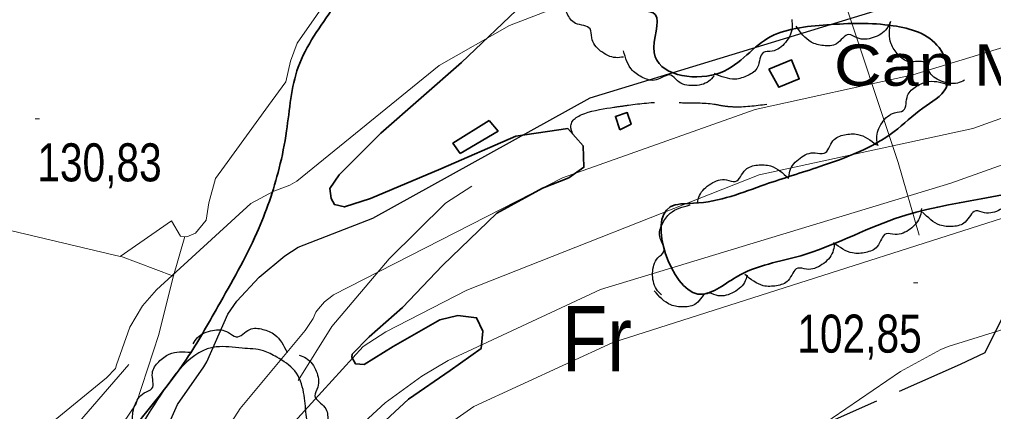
# Model space of a CAD drawing. Extents: x 483843 to 488449, y 4381269 to 4384483.
# Drawn here: x 486483.2 to 486707.3, y 4383232.7 to 4383322.9 of the extents above; entities that cross this region are included whole.
import ezdxf
from ezdxf.enums import TextEntityAlignment as Align

# ---------------------------------------------------------------- set-up
doc = ezdxf.new("R2010")
doc.units = 0
doc.header["$LTSCALE"] = 3.8
doc.linetypes.add('LONG_DASHED', pattern=[7.5, 6, -1.5])
for name, color, linetype, lineweight in [('13', 7, 'Continuous', 35), ('25', 7, 'LONG_DASHED', 25), ('27', 7, 'Continuous', 25), ('38', 7, 'Continuous', 25), ('47', 7, 'Continuous', 35), ('51', 7, 'Continuous', 13), ('6', 7, 'Continuous', 35), ('7', 7, 'Continuous', 13), ('8', 7, 'Continuous', 25), ('9', 7, 'Continuous', 13)]:
    doc.layers.add(name, color=color, linetype=linetype, lineweight=lineweight)
doc.layers.add('31', color=7, linetype='Continuous')
doc.layers.add('5', color=7, linetype='Continuous')

msp = doc.modelspace()

# ---------------------------------------------------------------- linework, layer by layer
at = {"layer": '13'}
msp.add_spline([(486780.88, 4383404.79), (486794.13, 4383455.03), (486806.75, 4383492.74), (486812.33, 4383499.64), (486814.71, 4383503.51), (486819.41, 4383506.81), (486825.21, 4383508.61), (486829.49, 4383508.62), (486831.66, 4383508.22), (486834.79, 4383506.67), (486839.23, 4383502.48), (486841.25, 4383491.57), (486838.33, 4383465.65), (486835.59, 4383431.7), (486834, 4383420.31), (486833.25, 4383414.77), (486832.97, 4383406.37), (486832.3, 4383401.5), (486829.47, 4383397.12), (486823.83, 4383396.67), (486809.94, 4383396.27), (486802.97, 4383396.6), (486796, 4383397.37), (486791.44, 4383398.19), (486788.79, 4383396.8), (486785.88, 4383392.64), (486784.6, 4383386.95), (486784.53, 4383376.98), (486784.84, 4383372.17), (486782.2, 4383361.03), (486774.71, 4383351.45), (486769.08, 4383335.85), (486761.59, 4383315.77), (486757.7, 4383301.05), (486738.21, 4383291.87), (486723.87, 4383286.22), (486684.72, 4383277.1), (486662.99, 4383268.56), (486648.14, 4383263.67), (486639.3, 4383259.75), (486632.91, 4383279.8), (486638.33, 4383280.62), (486654.82, 4383284.96), (486667.34, 4383289.06), (486684.49, 4383297.14), (486691.09, 4383302.53), (486696.41, 4383307.18), (486694.82, 4383316.43), (486684.24, 4383321.46), (486669.01, 4383321.68), (486655.38, 4383318.57), (486643.48, 4383310.34), (486629.22, 4383315.27), (486629.5, 4383324.04), (486622.3, 4383324.82), (486616.85, 4383326.7), (486612.21, 4383337.87), (486614.37, 4383347.45), (486644.42, 4383349.27), (486649.2, 4383384.92), (486651.66, 4383388.63), (486652.89, 4383395.9), (486652.14, 4383401.38), (486671.78, 4383415.81), (486678.55, 4383411.44), (486675.33, 4383401.28), (486669.84, 4383395.35), (486659.1, 4383373.67), (486670.12, 4383362.71), (486675.25, 4383359.48), (486683.36, 4383359.82), (486702.12, 4383364.88), (486729.49, 4383379.19), (486744.12, 4383389.71), (486750.48, 4383393.52), (486749.77, 4383396.53), (486731.96, 4383399.94), (486712.51, 4383419.8), (486725.33, 4383419.24), (486752.3, 4383411.05), (486765.39, 4383408.24), (486770.85, 4383407.04), (486780.7, 4383403.07)], degree=3, dxfattribs=at)
at = {"layer": '25'}
msp.add_lwpolyline([(486625.97, 4383203.81), (486659.6, 4383225.99), (486699.78, 4383243.65), (486705.44, 4383246.34), (486713.56, 4383262.73), (486722.5, 4383263.73), (486732.81, 4383265.76), (486750.38, 4383266.41), (486752.13, 4383263.16)], dxfattribs=at)
at = {"layer": '27'}
for points in [[(486610.86, 4384044.96), (486626.92, 4384050.28), (486637.16, 4384047.74), (486652.05, 4384044.37), (486668.53, 4384042.49), (486656.8, 4383988.7), (486633.28, 4383928.86), (486626.29, 4383912.38), (486620.95, 4383890.47), (486618.98, 4383873.39), (486617.47, 4383861.93), (486622.54, 4383859.83), (486631.45, 4383858.8), (486644.63, 4383856.29), (486649.12, 4383845.49), (486645.98, 4383835.48), (486644.53, 4383823.42), (486643.59, 4383804.83), (486644.04, 4383789.06), (486650.17, 4383776.97), (486661.43, 4383767.05), (486666.65, 4383759.32), (486665.61, 4383749.81), (486664.24, 4383748.18), (486659.87, 4383747.12), (486650.35, 4383747.78), (486629.58, 4383749.13), (486612.5, 4383751.02), (486592.66, 4383759.56), (486583.46, 4383745.88), (486580.74, 4383723.11), (486572.16, 4383689.84), (486560.68, 4383659.02), (486553.32, 4383631.81), (486543.18, 4383605.32), (486532.56, 4383576.21), (486523.53, 4383553.45), (486518.77, 4383540.54), (486501.4, 4383543.49), (486476.15, 4383556.3), (486468.29, 4383557.62), (486465.07, 4383557.96), (486462.29, 4383558.08), (486460.26, 4383557.81), (486439.29, 4383544.45), (486415.17, 4383526.49), (486391.53, 4383510.54), (486385.69, 4383506.57), (486377.62, 4383503.39), (486371.16, 4383503.41), (486344.21, 4383501.99), (486329.53, 4383482.99), (486328.89, 4383480.37), (486326.87, 4383475.75), (486312.85, 4383471.45), (486300.33, 4383482.51), (486290.76, 4383490.08), (486283.31, 4383493.56), (486272.61, 4383495.89), (486284, 4383520.94), (486252.05, 4383537.68), (486229.62, 4383543.55), (486216.83, 4383551.46), (486203.95, 4383558.48), (486174.8, 4383524.83), (486205.26, 4383519.21), (486220.9, 4383511.34), (486230.24, 4383508.13), (486241.13, 4383503.92), (486264.65, 4383495.7), (486250.48, 4383465.06), (486236.28, 4383432.55), (486231.27, 4383423.25), (486225.77, 4383410.64), (486214.94, 4383382.73), (486214.23, 4383380.42), (486219.38, 4383373.59), (486258.75, 4383355.69), (486297.13, 4383332.33), (486352.51, 4383306.4), (486336.13, 4383294.48), (486320.46, 4383268.89), (486317.3, 4383262.94), (486310.85, 4383257.93), (486295.11, 4383254.25), (486285.76, 4383251.31), (486282.23, 4383245.35), (486279.78, 4383236.83), (486280.35, 4383218.97), (486309.23, 4383192.29), (486315, 4383181.33)], [(486622.16, 4383314.27), (486620.38, 4383314.12), (486616.92, 4383315.65), (486614.86, 4383318.71), (486614.49, 4383320.74), (486611.17, 4383322.01), (486609.2, 4383324.25), (486608.34, 4383327.14), (486609.58, 4383331.95)], [(486660.89, 4383322.87), (486661.03, 4383321.1), (486659.47, 4383317.64), (486656.38, 4383315.62), (486654.35, 4383315.27), (486653.05, 4383311.96), (486650.79, 4383310.01), (486647.89, 4383309.18), (486643.09, 4383310.45)], [(486683.64, 4383322.4), (486682.81, 4383320.82), (486679.65, 4383318.73), (486675.96, 4383318.66), (486674.06, 4383319.43), (486671.2, 4383317.32), (486668.25, 4383316.88), (486665.34, 4383317.72), (486661.96, 4383321.35)], [(486700.69, 4383308.93), (486699.04, 4383308.28), (486695.27, 4383308.75), (486692.43, 4383311.1), (486691.5, 4383312.93), (486687.95, 4383313.19), (486685.42, 4383314.78), (486683.77, 4383317.31), (486683.57, 4383322.27)], [(486643.08, 4383309.94), (486641.81, 4383308.7), (486638.15, 4383307.69), (486634.62, 4383308.78), (486633.06, 4383310.11), (486629.68, 4383308.99), (486626.74, 4383309.49), (486624.24, 4383311.19), (486622.16, 4383315.7)], [(486680.76, 4383293.81), (486680.46, 4383295.56), (486681.7, 4383299.15), (486684.59, 4383301.44), (486686.57, 4383301.98), (486687.57, 4383305.39), (486689.64, 4383307.54), (486692.46, 4383308.63), (486697.35, 4383307.8)], [(486660.18, 4383286.3), (486660.47, 4383288.05), (486662.81, 4383291.03), (486666.29, 4383292.26), (486668.34, 4383292.12), (486670.4, 4383295.02), (486673.06, 4383296.37), (486676.08, 4383296.48), (486680.43, 4383294.1)], [(486639.19, 4383280.7), (486639.66, 4383282.42), (486642.29, 4383285.14), (486645.88, 4383286.01), (486647.9, 4383285.66), (486650.24, 4383288.34), (486653.03, 4383289.41), (486656.05, 4383289.21), (486660.13, 4383286.4)], [(486712.16, 4383283.52), (486711.63, 4383281.82), (486708.9, 4383279.19), (486705.28, 4383278.46), (486703.27, 4383278.88), (486700.84, 4383276.29), (486698.02, 4383275.32), (486695.01, 4383275.62), (486691.03, 4383278.59)], [(486630.95, 4383259.55), (486629.77, 4383260.87), (486628.89, 4383264.56), (486630.11, 4383268.06), (486631.49, 4383269.56), (486630.51, 4383272.98), (486631.12, 4383275.9), (486632.91, 4383278.33), (486637.49, 4383280.24)], [(486690.76, 4383279.46), (486690.48, 4383277.71), (486688.15, 4383274.71), (486684.67, 4383273.47), (486682.62, 4383273.61), (486680.58, 4383270.69), (486677.92, 4383269.33), (486674.9, 4383269.2), (486670.54, 4383271.57)], [(486670.7, 4383271.14), (486670.33, 4383269.4), (486667.86, 4383266.53), (486664.32, 4383265.46), (486662.28, 4383265.7), (486660.1, 4383262.89), (486657.38, 4383261.66), (486654.36, 4383261.68), (486650.12, 4383264.26)], [(486650.66, 4383264.09), (486650.03, 4383262.44), (486647.14, 4383259.97), (486643.48, 4383259.47), (486641.5, 4383260.02), (486638.91, 4383257.58), (486636.03, 4383256.78), (486633.05, 4383257.28), (486629.26, 4383260.48)], [(486523.13, 4383248.31), (486524.16, 4383249.75), (486527.59, 4383251.39), (486531.25, 4383250.95), (486533.02, 4383249.91), (486536.15, 4383251.61), (486539.14, 4383251.64), (486541.9, 4383250.4), (486544.74, 4383246.34)], [(486566.59, 4383165.19), (486559.21, 4383168.97), (486553.53, 4383170.18), (486550.54, 4383171.05), (486548.38, 4383172.28), (486543.56, 4383175.88), (486541.96, 4383179.65), (486542.24, 4383188.43), (486544.65, 4383204.83), (486548.1, 4383210.1), (486550.36, 4383221.33), (486550.39, 4383223.28), (486549.16, 4383232.07), (486548.56, 4383237.11), (486546.53, 4383242.09), (486542.38, 4383245.23), (486539.32, 4383246.7), (486534.38, 4383247.29), (486528.45, 4383247.6), (486514.92, 4383235.49), (486503.71, 4383217.19), (486497.82, 4383204.75), (486497.38, 4383200.03), (486496.93, 4383194.93), (486495.53, 4383185.95), (486495.78, 4383177.39), (486497.62, 4383169.41), (486498.94, 4383161.81), (486502.02, 4383151.94), (486512.14, 4383135.73), (486514.76, 4383130.14), (486517.17, 4383124.93), (486511.05, 4383122.02), (486506.05, 4383124.49), (486490.82, 4383134.91), (486487.26, 4383137.82), (486455.32, 4383113.66), (486442.37, 4383104.77), (486437.83, 4383086.67), (486430.34, 4383082.5), (486404.07, 4383086.78), (486395.79, 4383090.28), (486389.3, 4383093.22), (486382.29, 4383096.02), (486378.87, 4383098.55), (486381.09, 4383112.25), (486383.37, 4383119.49), (486385.11, 4383130.58), (486386.58, 4383138.73), (486382.65, 4383142.09), (486371.02, 4383149.11)], [(486510.1, 4383228.64), (486509.37, 4383230.26), (486509.66, 4383234.04), (486511.87, 4383237), (486513.65, 4383238.02), (486513.74, 4383241.57), (486515.21, 4383244.17), (486517.65, 4383245.95), (486522.59, 4383246.39)], [(486547.54, 4383245.71), (486549.16, 4383245), (486551.47, 4383241.99), (486551.8, 4383238.31), (486551.16, 4383236.36), (486553.46, 4383233.66), (486554.11, 4383230.74), (486553.47, 4383227.79), (486550.09, 4383224.16)]]:
    msp.add_spline(points, degree=3, dxfattribs=at)
at = {"layer": '38', "linetype": 'LONG_DASHED'}
msp.add_spline([(486610.54, 4383296.52), (486610.09, 4383297.89), (486619.96, 4383302.72), (486623.34, 4383303.2), (486631.76, 4383303.9), (486635.73, 4383303.77), (486643.01, 4383303.44), (486645.33, 4383303.03), (486647.35, 4383302.85), (486655.16, 4383303.42)], degree=3, dxfattribs=at)
at = {"layer": '47'}
for points in [[(486655.65, 4383311.51), (486660.86, 4383313.62), (486662.64, 4383309.22), (486657.94, 4383307.32)], [(486621.31, 4383297.52), (486620.31, 4383300.61), (486623.04, 4383301.5), (486623.91, 4383298.8)]]:
    msp.add_lwpolyline(points, close=True, dxfattribs=at)
for points in [[(486584.62, 4383292.05), (486582.93, 4383294.47), (486591.25, 4383299.68)], [(486591.25, 4383299.68), (486593.32, 4383297.25), (486584.62, 4383292.05)]]:
    msp.add_lwpolyline(points, dxfattribs=at)
at = {"layer": '51'}
for p, q in [((486540.51, 4383303.14), (486530.33, 4383289.17)), ((486540.51, 4383303.14), (486530.33, 4383289.17)), ((486518.61, 4383263.9), (486506.44, 4383268.49)), ((486515.21, 4383250.42), (486510.03, 4383234.51))]:
    msp.add_line(p, q, dxfattribs=at)
for points in [[(486469.1, 4383389.53), (486577.07, 4383362.46), (486555.98, 4383330.28), (486547.09, 4383317.42), (486545.53, 4383313.32), (486544.48, 4383308.6), (486540.51, 4383303.14)], [(486690.22, 4383273.27), (486685.43, 4383290), (486672.13, 4383329.96), (486653.36, 4383381.93), (486649.13, 4383380.26)], [(486437.22, 4383285.73), (486471.24, 4383276.64), (486506.32, 4383268.41), (486518.14, 4383276.57), (486520.19, 4383273.09), (486521.69, 4383272.91), (486523.65, 4383273.79), (486526.09, 4383276.75), (486526.75, 4383280.72), (486528.26, 4383286.33), (486530.33, 4383289.17)], [(486547.33, 4383239.9), (486555.08, 4383252.32), (486568.21, 4383267.82), (486581.23, 4383280.69), (486587.29, 4383284.58)], [(486515.21, 4383250.42), (486518.47, 4383263.43), (486521.19, 4383272.97)], [(486486.84, 4383223.81), (486496.53, 4383229.9), (486508.36, 4383243.54)], [(486421.45, 4383238.51), (486495.31, 4383212.81), (486510.03, 4383234.51)]]:
    msp.add_lwpolyline(points, dxfattribs=at)
at = {"layer": '6'}
msp.add_lwpolyline([(486599.1, 4383326.49), (486584.93, 4383313.02), (486566.33, 4383296.79), (486556.72, 4383287.17), (486554.58, 4383284.05), (486554.88, 4383281.74), (486555.64, 4383280.33), (486557.96, 4383279.81), (486563.98, 4383281.74), (486580.17, 4383288.52), (486597.42, 4383296.04), (486609.35, 4383297.86), (486612.87, 4383293.86), (486613.06, 4383288.93), (486609.6, 4383286.5), (486603.52, 4383284.14), (486593.03, 4383278.36), (486580.51, 4383266.34), (486571.33, 4383256.67), (486563.64, 4383249.94), (486559.74, 4383245.96), (486559.63, 4383245.23), (486560.47, 4383243.73), (486562.47, 4383243.55), (486569.19, 4383247.72), (486579.91, 4383253.86), (486584.04, 4383254.81), (486588.35, 4383254.3), (486589.81, 4383251.21), (486589.41, 4383247.2), (486582.25, 4383242.17), (486572.68, 4383235.58), (486562.22, 4383225.85)], dxfattribs=at)
msp.add_spline([(486616.4, 4383398.76), (486609.53, 4383398.32), (486605.76, 4383397.51), (486603.64, 4383396.68), (486601.06, 4383394.53), (486581.77, 4383363.75), (486567.92, 4383345.34), (486555.49, 4383325.84), (486547.31, 4383311.93), (486544.63, 4383297.26), (486542.93, 4383288.69), (486537.77, 4383273.81), (486528.83, 4383256.87), (486521.61, 4383244.78), (486506.85, 4383225.48), (486495.82, 4383205.81), (486490.76, 4383183.12), (486490.75, 4383171.7), (486494.48, 4383158.89), (486500.87, 4383143.53), (486507.02, 4383132), (486513.34, 4383122.31), (486520.6, 4383114.98), (486524.69, 4383110.49), (486524.72, 4383107.37), (486523.98, 4383102.8), (486520.48, 4383093.44), (486518.01, 4383088.42), (486514.34, 4383083.16), (486511.09, 4383077.17), (486509.02, 4383072.98), (486506.76, 4383070.57), (486504.86, 4383068.89), (486504.98, 4383068.05), (486506.45, 4383067.29), (486509.87, 4383067.88), (486515.23, 4383069.39), (486530.79, 4383072.38), (486552.79, 4383077.34), (486574.89, 4383083.42), (486585.15, 4383087.17), (486588.99, 4383088.06), (486590.1, 4383087.94), (486592.93, 4383085.95), (486593.37, 4383080.97), (486593.38, 4383076.71), (486593.42, 4383068.62), (486592.95, 4383062.34)], degree=3, dxfattribs=at)
at = {"layer": '7'}
for p, q in [((486486.76, 4383300.04), (486487.76, 4383300.04)), ((486688.96, 4383262.33), (486689.96, 4383262.33))]:
    msp.add_line(p, q, dxfattribs=at)
at = {"layer": '8'}
msp.add_lwpolyline([(486517.96, 4383230.93), (486519.53, 4383234.38), (486525.61, 4383243), (486526.3, 4383244.17), (486531.1, 4383255.15), (486533.18, 4383258.1), (486538.32, 4383263.67), (486544.2, 4383268.56), (486547.33, 4383270.55), (486564.49, 4383277.21), (486614.52, 4383304.9), (486709.81, 4383334.05)], dxfattribs=at)
at = {"layer": '9'}
for points in [[(486479.53, 4383221.15), (486503.22, 4383240.48), (486505.26, 4383242.6), (486505.47, 4383243.51), (486508.59, 4383252.15), (486511.49, 4383257.02), (486514.67, 4383260.76), (486536.41, 4383280.6), (486541.72, 4383283.44), (486545.37, 4383284.78), (486547.03, 4383285.7), (486579.76, 4383312.32), (486595.98, 4383321.52), (486606.13, 4383325.46), (486636.2, 4383333.92), (486660.46, 4383337.43), (486708.29, 4383348.58), (486760.42, 4383353.62), (486812.91, 4383348.73), (486850.69, 4383338.27)], [(486747.28, 4383328.04), (486688.74, 4383310.15), (486652.5, 4383302.18), (486608.17, 4383286.47), (486555.46, 4383259.59), (486555.02, 4383259.29), (486553.39, 4383257.94), (486551.96, 4383256.39), (486551.39, 4383255.57), (486550.73, 4383254.16), (486548.9, 4383251.39), (486533.92, 4383233.42), (486531.33, 4383229.36)], [(486758.63, 4383317.88), (486702.56, 4383297.86), (486653.42, 4383287.15), (486586.13, 4383260.64), (486567.51, 4383251.07), (486562.29, 4383247.72), (486545.61, 4383229.46)], [(486754.51, 4383305.59), (486697.49, 4383285.25), (486616.85, 4383260.78), (486581.82, 4383244.49), (486575.75, 4383240.86), (486567.36, 4383234.72), (486556.85, 4383225.11)], [(486545.5, 4383167.55), (486543.76, 4383168.96), (486542.73, 4383170.26), (486539.38, 4383173.54), (486538.86, 4383174.22), (486538.39, 4383175.29), (486538.17, 4383177.37), (486539.89, 4383186.83), (486542.33, 4383193.75), (486544.63, 4383197.75), (486550.47, 4383205.27), (486559.58, 4383214.21), (486587.7, 4383233.93), (486619.7, 4383248.63), (486743.33, 4383288.05)], [(486718.87, 4383254.53), (486696.91, 4383247.71), (486695.2, 4383246.97), (486685.97, 4383241.97), (486667.09, 4383229.05)]]:
    msp.add_lwpolyline(points, dxfattribs=at)

# ---------------------------------------------------------------- texts
at = {"layer": '31', "width": 0.85}
msp.add_text('Fr', height=15, dxfattribs=at).set_placement((486616.08, 4383241.98), align=Align.CENTER)
at = {"layer": '5', "width": 1.2}
msp.add_text('Can Marro', height=9.5, dxfattribs=at).set_placement((486670.61, 4383307.66))
at = {"layer": '7', "width": 0.8}
for s, p in [('130,83', (486487.26, 4383285.67)), ('102,85', (486662.19, 4383246.28))]:
    msp.add_text(s, height=8.75, dxfattribs=at).set_placement(p)

doc.saveas('drawing.dxf')
